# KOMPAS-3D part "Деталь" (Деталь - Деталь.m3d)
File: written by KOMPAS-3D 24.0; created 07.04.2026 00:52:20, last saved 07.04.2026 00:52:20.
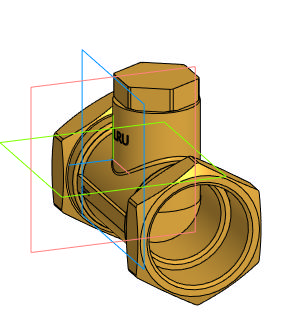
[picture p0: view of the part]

Document properties: Автор: tyuri; Полное имя файла: D:\Аутсорс\VBA0000E-T Клапан балансировочный автоматический DN.ru\DN25\Исходные файлы\Деталь - Деталь.m3d

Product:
- Body: Твердое тело1  | qty 1
- Part/product: Деталь
    additional columns: Типовые

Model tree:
1. Твердое тело1  (labels: Твердое тело1)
